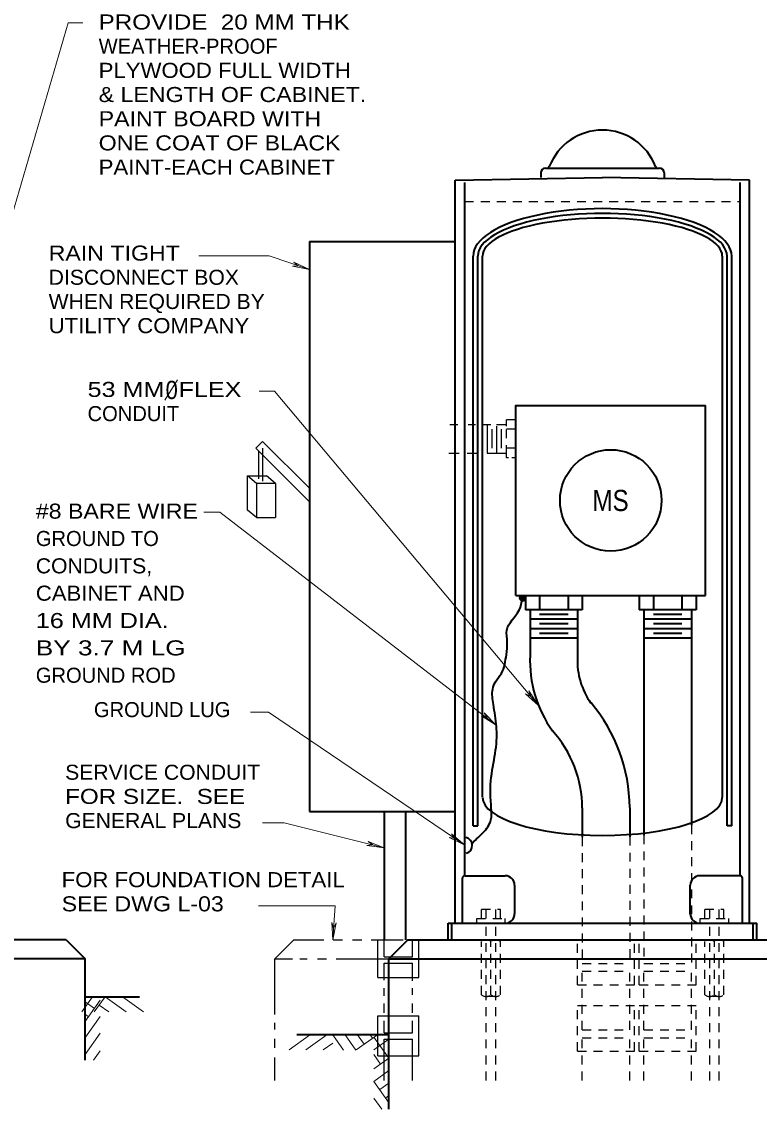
# Model space of a CAD drawing. Extents: x 312583 to 312854, y 144419 to 144597.
# Drawn here: x 312731.2 to 312768.4, y 144512.3 to 144567.2 of the extents above; entities that cross this region are included whole.
import ezdxf
from ezdxf.enums import TextEntityAlignment as Align

# ---------------------------------------------------------------- set-up
doc = ezdxf.new("R2010")
doc.units = 0
doc.header["$LTSCALE"] = 0.3
doc.linetypes.add('SHORT_DASHED', pattern=[2.7, 1.5, -1.2])
doc.layers.add('1', color=7, linetype='Continuous', lineweight=25)
doc.layers.add('2', color=7, linetype='Continuous', lineweight=13)

msp = doc.modelspace()

# ---------------------------------------------------------------- linework, layer by layer
at = {"layer": '1', "lineweight": 40}
for p, q in [((312757.3543, 144559.527), (312757.3543, 144559.2893)), ((312757.5997, 144559.7646), (312763.3497, 144559.7646)), ((312763.5873, 144559.527), (312763.5873, 144559.2893)), ((312753.0457, 144559.159), (312760.4747, 144559.2893)), ((312753.0457, 144521.6613), (312753.0457, 144559.159)), ((312753.521, 144524.061), (312753.521, 144559.044)), ((312767.896, 144559.159), (312760.4747, 144559.2893)), ((312767.4207, 144524.061), (312767.4207, 144559.044)), ((312767.896, 144521.6613), (312767.896, 144559.159)), ((312745.678, 144556.0616), (312745.678, 144527.2963)), ((312745.678, 144556.0616), (312753.0457, 144556.0616)), ((312749.2123, 144556.0616), (312750.7687, 144556.0616)), ((312753.9427, 144526.5756), (312753.9427, 144555.3256)), ((312754.1803, 144526.5756), (312754.1803, 144555.3256)), ((312754.4257, 144528.017), (312754.4257, 144555.3256)), ((312766.5237, 144528.017), (312766.5237, 144555.3256)), ((312766.7613, 144526.5756), (312766.7613, 144555.3256)), ((312766.999, 144526.5756), (312766.999, 144555.3256)), ((312765.6803, 144538.206), (312765.6803, 144547.7893)), ((312756.097, 144538.206), (312765.6803, 144538.206)), ((312756.58, 144538.206), (312756.58, 144537.4853)), ((312757.3007, 144538.206), (312757.3007, 144537.4853)), ((312758.7343, 144538.206), (312758.7343, 144537.4853)), ((312759.455, 144538.206), (312759.455, 144537.4853)), ((312762.33, 144538.206), (312762.33, 144537.4853)), ((312763.0507, 144538.206), (312763.0507, 144537.4853)), ((312764.4843, 144538.206), (312764.4843, 144537.4853)), ((312765.205, 144538.206), (312765.205, 144537.4853)), ((312759.455, 144537.4853), (312756.58, 144537.4853)), ((312756.8177, 144537.4853), (312756.8177, 144535.1776)), ((312759.2173, 144537.4853), (312759.2173, 144535.0703)), ((312765.205, 144537.4853), (312762.33, 144537.4853)), ((312762.5677, 144537.4853), (312762.5677, 144526.1003)), ((312764.9673, 144537.4853), (312764.9673, 144526.614)), ((312759.2173, 144537.01), (312756.8177, 144537.01)), ((312758.7343, 144537.2476), (312757.3007, 144537.2476)), ((312764.9673, 144537.01), (312762.5677, 144537.01)), ((312764.4843, 144537.2476), (312763.0507, 144537.2476)), ((312759.2173, 144536.527), (312756.8177, 144536.527)), ((312758.7343, 144536.7646), (312757.3007, 144536.7646)), ((312764.9673, 144536.527), (312762.5677, 144536.527)), ((312764.4843, 144536.7646), (312763.0507, 144536.7646)), ((312759.2173, 144536.0516), (312756.8177, 144536.0516)), ((312758.7343, 144536.2893), (312757.3007, 144536.2893)), ((312764.9673, 144536.0516), (312762.5677, 144536.0516)), ((312764.4843, 144536.2893), (312763.0507, 144536.2893)), ((312745.678, 144527.2963), (312753.0457, 144527.2963)), ((312749.45, 144527.2963), (312749.45, 144520.8256)), ((312750.531, 144527.2963), (312750.531, 144520.8256)), ((312759.455, 144527.4803), (312759.455, 144526.0083)), ((312761.847, 144527.4803), (312761.847, 144526.0313)), ((312753.9427, 144526.5756), (312754.1803, 144526.5756)), ((312766.999, 144526.5756), (312766.7613, 144526.5756)), ((312753.406, 144521.6613), (312753.406, 144523.9383)), ((312753.521, 144524.061), (312755.5603, 144524.061)), ((312767.4207, 144524.061), (312765.3813, 144524.061)), ((312767.5433, 144521.6613), (312767.5433, 144523.9383)), ((312756.0433, 144522.1443), (312756.0433, 144523.578)), ((312764.906, 144522.1443), (312764.906, 144523.578)), ((312752.6853, 144521.6613), (312768.2563, 144521.6613)), ((312752.6853, 144520.8256), (312752.6853, 144521.6613)), ((312752.8693, 144520.8256), (312752.8693, 144521.6613)), ((312768.08, 144520.8256), (312768.08, 144521.6613)), ((312768.2563, 144520.8256), (312768.2563, 144521.6613)), ((312733.4019, 144520.8256), (312712.3185, 144520.8256)), ((312733.4019, 144520.8256), (312734.3602, 144519.8673)), ((312750.646, 144520.8256), (312749.6877, 144519.8673)), ((312734.3602, 144519.8673), (312711.3602, 144519.8673)), ((312734.3602, 144514.746), (312734.3602, 144519.8673)), ((312749.6877, 144512.2775), (312749.6877, 144519.8673)), ((312734.3602, 144517.9506), (312737.1049, 144517.9506)), ((312749.6953, 144516.034), (312745.0417, 144516.034))]:
    msp.add_line(p, q, dxfattribs=at)
at = {"layer": '1', "linetype": 'SHORT_DASHED'}
for p, q in [((312753.521, 144558.078), (312767.4207, 144558.078)), ((312764.9673, 144526.614), (312764.9673, 144519.6373)), ((312759.455, 144526.0083), (312759.455, 144519.6373)), ((312761.847, 144526.0313), (312761.847, 144519.6373)), ((312762.5677, 144526.1003), (312762.5677, 144519.6373)), ((312754.602, 144521.9066), (312754.602, 144522.382)), ((312755.085, 144521.9066), (312755.085, 144522.382)), ((312755.3227, 144521.9066), (312755.3227, 144522.382)), ((312765.8873, 144521.9066), (312765.8873, 144522.382)), ((312766.3627, 144521.9066), (312766.3627, 144522.382)), ((312766.6003, 144521.9066), (312766.6003, 144522.382)), ((312754.1267, 144521.9066), (312755.5603, 144521.9066)), ((312754.1267, 144521.6613), (312754.1267, 144521.9066)), ((312754.602, 144513.734), (312754.602, 144521.6613)), ((312755.085, 144513.734), (312755.085, 144521.6613)), ((312755.5603, 144521.6613), (312755.5603, 144521.9066)), ((312765.4043, 144521.9066), (312766.8457, 144521.9066)), ((312765.4043, 144521.6613), (312765.4043, 144521.9066)), ((312765.8873, 144513.734), (312765.8873, 144521.6613)), ((312766.3627, 144513.734), (312766.3627, 144521.6613)), ((312766.8457, 144521.6613), (312766.8457, 144521.9066)), ((312754.3643, 144518.0503), (312754.3643, 144520.7413)), ((312754.8397, 144518.0503), (312754.8397, 144520.8256)), ((312755.3227, 144518.0503), (312755.3227, 144520.7413)), ((312759.2173, 144518.5563), (312759.2173, 144520.8256)), ((312762.0923, 144518.5563), (312762.0923, 144520.8256)), ((312762.33, 144518.5563), (312762.33, 144520.8256)), ((312765.205, 144518.5563), (312765.205, 144520.8256)), ((312765.642, 144518.0503), (312765.642, 144520.7413)), ((312766.125, 144518.0503), (312766.125, 144520.8256)), ((312766.6003, 144518.0503), (312766.6003, 144520.7413)), ((312759.455, 144519.6373), (312761.847, 144519.6373)), ((312762.5677, 144519.6373), (312764.9673, 144519.6373)), ((312759.455, 144519.2386), (312761.847, 144519.2386)), ((312759.455, 144516.287), (312759.455, 144519.2386)), ((312761.847, 144516.287), (312761.847, 144519.2386)), ((312762.5677, 144519.2386), (312764.9673, 144519.2386)), ((312762.5677, 144516.287), (312762.5677, 144519.2386)), ((312764.9673, 144516.287), (312764.9673, 144519.2386)), ((312759.2173, 144518.5563), (312762.0923, 144518.5563)), ((312762.33, 144518.5563), (312765.205, 144518.5563)), ((312755.085, 144517.9736), (312754.602, 144517.9736)), ((312766.3627, 144517.9736), (312765.8873, 144517.9736)), ((312759.2173, 144517.506), (312762.0923, 144517.506)), ((312759.2173, 144515.206), (312759.2173, 144517.506)), ((312762.0923, 144515.206), (312762.0923, 144517.506)), ((312762.33, 144517.506), (312765.205, 144517.506)), ((312762.33, 144515.206), (312762.33, 144517.506)), ((312765.205, 144515.206), (312765.205, 144517.506)), ((312759.455, 144516.287), (312761.847, 144516.287)), ((312762.5677, 144516.287), (312764.9673, 144516.287)), ((312759.455, 144515.8883), (312761.847, 144515.8883)), ((312759.455, 144513.734), (312759.455, 144515.8883)), ((312761.847, 144513.734), (312761.847, 144515.8883)), ((312762.5677, 144515.8883), (312764.9673, 144515.8883)), ((312762.5677, 144513.734), (312762.5677, 144515.8883)), ((312764.9673, 144513.734), (312764.9673, 144515.8883)), ((312759.2173, 144515.206), (312762.0923, 144515.206)), ((312762.33, 144515.206), (312765.205, 144515.206))]:
    msp.add_line(p, q, dxfattribs=at)
at = {"layer": '1'}
for p, q in [((312752.7697, 144546.831), (312753.1683, 144546.831)), ((312753.6897, 144546.831), (312754.0577, 144546.831)), ((312754.418, 144546.831), (312754.8397, 144546.831)), ((312754.6633, 144545.3896), (312754.6633, 144546.831)), ((312755.131, 144546.831), (312755.6217, 144546.831)), ((312755.1387, 144545.3896), (312755.1387, 144546.7543)), ((312756.097, 144547.0686), (312755.6217, 144547.0686)), ((312755.6217, 144546.7543), (312755.6217, 144547.0686)), ((312754.4257, 144545.635), (312754.4257, 144546.5933)), ((312754.901, 144545.635), (312754.901, 144546.5933)), ((312755.384, 144545.635), (312755.384, 144546.5933)), ((312756.097, 144546.5933), (312755.6217, 144546.5933)), ((312755.6217, 144546.1486), (312755.6217, 144546.5703)), ((312745.678, 144542.9363), (312742.9717, 144545.6426)), ((312743.3167, 144545.6426), (312743.3167, 144543.9636)), ((312755.6217, 144545.152), (312755.6217, 144545.7883)), ((312756.097, 144545.635), (312755.6217, 144545.635)), ((312743.125, 144544.094), (312743.125, 144545.5046)), ((312752.716, 144545.3896), (312753.245, 144545.3896)), ((312753.636, 144545.3896), (312754.1573, 144545.3896)), ((312754.6557, 144545.3896), (312755.6217, 144545.3896)), ((312755.729, 144545.152), (312755.6217, 144545.152)), ((312756.097, 144545.152), (312755.89, 144545.152)), ((312743.01, 144543.8563), (312742.5577, 144544.232)), ((312743.9683, 144543.8563), (312743.516, 144544.232)), ((312743.9683, 144543.8563), (312743.01, 144543.8563)), ((312743.9683, 144543.8563), (312743.9683, 144542.1313)), ((312743.01, 144542.1313), (312742.5577, 144542.507)), ((312744.896, 144520.8256), (312743.9377, 144519.8673)), ((312744.896, 144520.8256), (312746.4063, 144520.8256)), ((312746.8817, 144520.8256), (312747.3493, 144520.8256)), ((312747.8477, 144520.8256), (312748.323, 144520.8256)), ((312748.7907, 144520.8256), (312750.4083, 144520.8256)), ((312749.1357, 144518.932), (312749.1357, 144520.8256)), ((312749.45, 144519.9746), (312749.45, 144520.8256)), ((312750.8913, 144519.9746), (312750.8913, 144520.8256)), ((312751.2057, 144518.932), (312751.2057, 144520.8256)), ((312745.2027, 144519.8673), (312745.5707, 144519.8673)), ((312746.092, 144519.8673), (312746.5367, 144519.8673)), ((312747.035, 144519.8673), (312749.6877, 144519.8673)), ((312749.45, 144519.9746), (312750.8913, 144519.9746)), ((312749.45, 144519.6526), (312750.8913, 144519.6526)), ((312749.45, 144518.7863), (312749.45, 144519.6526)), ((312750.8913, 144518.7633), (312750.8913, 144519.6526)), ((312749.1357, 144518.932), (312751.2057, 144518.932)), ((312749.45, 144518.0043), (312749.45, 144518.3953)), ((312750.8913, 144518.058), (312750.8913, 144518.3953)), ((312749.45, 144517.138), (312749.45, 144517.6133)), ((312750.8913, 144517.138), (312750.8913, 144517.6133)), ((312743.9377, 144516.3023), (312743.9377, 144516.6396)), ((312749.1357, 144514.976), (312749.1357, 144516.9846)), ((312749.1357, 144516.9846), (312751.2057, 144516.9846)), ((312749.45, 144516.1336), (312749.45, 144516.747)), ((312750.8913, 144516.1336), (312750.8913, 144516.747)), ((312751.2057, 144514.976), (312751.2057, 144516.9846)), ((312749.45, 144516.1336), (312750.8913, 144516.1336)), ((312743.9377, 144515.3823), (312743.9377, 144515.827)), ((312749.45, 144515.8116), (312750.8913, 144515.8116)), ((312749.45, 144513.734), (312749.45, 144515.8116)), ((312750.8913, 144513.734), (312750.8913, 144515.8116)), ((312749.1357, 144514.976), (312751.2057, 144514.976)), ((312743.9377, 144513.734), (312743.9377, 144514.884))]:
    msp.add_line(p, q, dxfattribs=at)
at = {"layer": '1', "lineweight": 40}
for points in [[(312756.097, 144538.206), (312756.097, 144547.7893), (312765.6803, 144547.7893)], [(312750.646, 144520.8256), (312769.3932, 144520.8256), (312838.4507, 144520.8256)], [(312749.6877, 144519.8673), (312769.3932, 144519.8673), (312839.409, 144519.8673)]]:
    msp.add_lwpolyline(points, dxfattribs=at)
at = {"layer": '1'}
for points in [[(312745.678, 144543.611), (312743.3167, 144545.98), (312742.9717, 144545.6426)], [(312742.5577, 144542.507), (312742.5577, 144544.232), (312743.516, 144544.232)], [(312743.01, 144543.8563), (312743.01, 144542.1313), (312743.9683, 144542.1313)], [(312743.9377, 144517.0613), (312743.9377, 144519.8673), (312744.8347, 144519.8673)]]:
    msp.add_lwpolyline(points, dxfattribs=at)
at = {"layer": '1', "linetype": 'SHORT_DASHED'}
for points in [[(312754.3643, 144521.9066), (312754.3643, 144522.382), (312755.3227, 144522.382)], [(312765.642, 144521.9066), (312765.642, 144522.382), (312766.6003, 144522.382)]]:
    msp.add_lwpolyline(points, dxfattribs=at)
at = {"layer": '1', "lineweight": 40}
for centre, radius in [((312760.8915, 144542.9967), 2.5622), ((312756.443, 144538.0651), 0.1358), ((312756.443, 144538.0651), 0.1174), ((312756.443, 144538.0651), 0.1057), ((312756.443, 144538.0651), 0.0822), ((312756.443, 144538.0651), 0.0575), ((312756.443, 144538.0651), 0.0403), ((312756.443, 144538.0651), 0.0282), ((312756.443, 144538.0651), 0.0197), ((312756.443, 144538.0651), 0.0138)]:
    msp.add_circle(centre, radius, dxfattribs=at)
for centre, radius, start, end in [((312760.4718, 144558.8092), 2.875, 21.1002, 158.90079), ((312757.5968, 144559.5279), 0.2396, 90, 180), ((312757.6778, 144559.8873), 0.1198, 270, 338.8998), ((312763.2658, 144559.8873), 0.1198, 201.1002, 270), ((312763.3468, 144559.5279), 0.2396, 0, 90), ((312762.864, 144534.9026), 6.0515, 177.41325, 215.63484), ((312762.864, 144534.9026), 3.6557, 177.41325, 215.63484), ((312753.5213, 144527.4239), 8.3288, 0.55271, 40.01494), ((312753.5213, 144527.4239), 5.933, 0.55379, 41.7798), ((312753.494, 144525.5862), 0.4076, 285.15764, 77.61644), ((312753.5239, 144523.9402), 0.1198, 90, 180), ((312755.5603, 144523.5808), 0.4792, 0, 90), ((312765.3833, 144523.5808), 0.4792, 90, 180), ((312767.4197, 144523.9402), 0.1198, 0, 90), ((312755.5603, 144522.1433), 0.4792, 270, 0), ((312765.3833, 144522.1433), 0.4792, 180, 270)]:
    msp.add_arc(centre, radius, start, end, dxfattribs=at)
at = {"layer": '1', "linetype": 'SHORT_DASHED'}
for centre, radius, start, end in [((312754.602, 144520.4379), 0.3858, 51.61151, 128.38849), ((312755.0812, 144520.4045), 0.4125, 54.49327, 125.50673), ((312765.8835, 144520.4379), 0.3858, 51.61151, 128.38849), ((312766.3627, 144520.4045), 0.4125, 54.49327, 125.50673), ((312754.602, 144518.3823), 0.4125, 234.49327, 305.50673), ((312755.0812, 144518.3823), 0.4125, 234.49327, 305.50673), ((312765.8835, 144518.3823), 0.4125, 234.49327, 305.50673), ((312766.3627, 144518.3823), 0.4125, 234.49327, 305.50673)]:
    msp.add_arc(centre, radius, start, end, dxfattribs=at)
at = {"layer": '1', "lineweight": 40}
for centre, major_axis, ratio, start_param, end_param in [((312760.4723, 144555.3256), (6.5286, 0), 0.366972, 6.2831853, 9.424778), ((312760.4723, 144555.3256), (6.2891, 0), 0.342857, 6.2831853, 9.424778), ((312760.4723, 144555.3256), (6.0495, 0), 0.316832, 6.2831853, 9.424778), ((312760.4723, 144528.0131), (6.0495, 0), 0.316832, 3.1415927, 6.2831853)]:
    msp.add_ellipse(centre, major_axis=major_axis, ratio=ratio, start_param=start_param, end_param=end_param, dxfattribs=at)
msp.add_spline([(312753.889, 144525.694), (312754.119, 144525.9163), (312754.4563, 144526.2383), (312754.8397, 144526.8746), (312754.8627, 144527.488), (312754.8167, 144528.3006), (312754.97, 144529.742), (312755.1387, 144531.0376), (312755.0543, 144532.1416), (312754.97, 144532.7013), (312754.9317, 144533.4833), (312755.0697, 144533.8436), (312755.3687, 144534.273), (312755.6217, 144535.2083), (312755.6677, 144535.8446), (312755.6447, 144536.458), (312756.2657, 144537.4623), (312756.442, 144538.068)], degree=3, dxfattribs=at)
at = {"layer": '2'}
for p, q in [((312733.5012, 144567.0972), (312728.8555, 144551.1933)), ((312734.2372, 144567.0972), (312733.5012, 144567.0972)), ((312743.6463, 144555.3333), (312740.1043, 144555.3333)), ((312745.678, 144554.6433), (312743.6463, 144555.3333)), ((312744.896, 144555.0266), (312745.1183, 144554.835)), ((312745.678, 144554.6433), (312744.896, 144555.0266)), ((312744.8193, 144554.8196), (312745.1183, 144554.835)), ((312745.678, 144554.6433), (312744.8193, 144554.8196)), ((312738.3844, 144548.0607), (312739.0207, 144549.0804)), ((312741.1523, 144542.4038), (312740.3596, 144542.4038)), ((312741.1523, 144542.4038), (312755.108, 144531.6663)), ((312756.5953, 144533.2456), (312756.8637, 144533.1076)), ((312757.247, 144532.6553), (312756.5953, 144533.2456)), ((312756.764, 144533.3913), (312756.8637, 144533.1076)), ((312757.247, 144532.6553), (312756.764, 144533.3913)), ((312742.7124, 144532.3103), (312743.6233, 144532.3103)), ((312743.6233, 144532.3103), (312753.521, 144525.6096)), ((312754.3643, 144532.1263), (312754.6557, 144532.0343)), ((312755.108, 144531.6663), (312754.3643, 144532.1263)), ((312754.5023, 144532.2873), (312754.6557, 144532.0343)), ((312755.108, 144531.6663), (312754.5023, 144532.2873)), ((312743.3167, 144526.7366), (312744.4053, 144526.7366)), ((312744.4053, 144526.7366), (312749.45, 144525.464)), ((312752.739, 144525.9853), (312753.0303, 144525.9316)), ((312753.521, 144525.6096), (312752.739, 144525.9853)), ((312752.854, 144526.1693), (312753.0303, 144525.9316)), ((312753.521, 144525.6096), (312752.854, 144526.1693)), ((312748.5837, 144525.5866), (312748.8827, 144525.6173)), ((312749.45, 144525.464), (312748.5837, 144525.5866)), ((312748.645, 144525.7936), (312748.8827, 144525.6173)), ((312749.45, 144525.464), (312748.645, 144525.7936)), ((312743.1135, 144522.543), (312746.989, 144522.543)), ((312746.989, 144522.543), (312746.8663, 144520.8563)), ((312746.8203, 144521.6996), (312746.9047, 144521.416)), ((312746.8663, 144520.8256), (312746.8203, 144521.6996)), ((312746.8663, 144520.8256), (312747.035, 144521.6843)), ((312747.035, 144521.6843), (312746.9047, 144521.416)), ((312734.7359, 144517.9506), (312734.1915, 144517.1916)), ((312735.1269, 144517.782), (312734.3525, 144516.6933)), ((312734.3602, 144517.6976), (312734.8279, 144517.368)), ((312735.3645, 144517.9506), (312734.8202, 144517.1916)), ((312736.4302, 144517.1916), (312735.3645, 144517.9506)), ((312737.3119, 144517.1916), (312736.2462, 144517.9506)), ((312735.5562, 144517.1916), (312735.0655, 144517.5366)), ((312734.3602, 144517.069), (312734.5289, 144516.9463)), ((312735.1269, 144516.954), (312734.3832, 144515.9113)), ((312735.1269, 144516.1106), (312734.3602, 144515.0373)), ((312744.6507, 144515.275), (312745.6933, 144516.011)), ((312745.494, 144515.275), (312746.5673, 144516.034)), ((312746.8587, 144516.0263), (312747.403, 144515.2596)), ((312747.4873, 144516.0263), (312748.0317, 144515.2596)), ((312748.047, 144515.275), (312749.1127, 144516.034)), ((312748.116, 144516.0263), (312748.4457, 144515.5586)), ((312748.7447, 144516.0263), (312748.8597, 144515.8576)), ((312749.358, 144516.034), (312749.358, 144516.0416)), ((312746.3757, 144515.275), (312746.8587, 144515.62)), ((312748.9287, 144515.919), (312749.6953, 144514.8533)), ((312748.9287, 144515.275), (312749.6953, 144515.8193)), ((312735.1269, 144515.229), (312734.7819, 144514.746)), ((312748.9287, 144515.0373), (312749.2737, 144514.5543)), ((312749.6953, 144514.8533), (312748.9287, 144514.309)), ((312749.6953, 144514.2246), (312748.9287, 144513.6803)), ((312748.9287, 144513.6803), (312749.703, 144512.5916)), ((312749.6953, 144513.596), (312749.2277, 144513.2663)), ((312748.9287, 144512.8446), (312749.3361, 144512.2775)), ((312749.6953, 144512.9673), (312749.519, 144512.8446))]:
    msp.add_line(p, q, dxfattribs=at)
msp.add_lwpolyline([(312743.148, 144548.5176), (312743.9223, 144548.5176), (312757.247, 144532.6553)], dxfattribs=at)

# ---------------------------------------------------------------- texts
at = {"layer": '1'}
for s, p in [('GROUND TO', (312731.8702, 144540.6983)), ('GROUND ROD', (312731.8702, 144533.7983))]:
    msp.add_text(s, height=0.76, dxfattribs=at).set_placement(p)
for s, width, p in [('CONDUITS,', 1.05, (312731.8702, 144539.3183)), ('CABINET AND', 1.1, (312731.8702, 144537.9383)), ('16 MM DIA.', 1.25, (312731.8702, 144536.5583)), ('BY 3.7 M LG', 1.3, (312731.8702, 144535.1783))]:
    msp.add_text(s, height=0.76, dxfattribs=dict(at, width=width)).set_placement(p)
at = {"layer": '2'}
for s, width, p in [('PROVIDE  20 MM THK', 1.2, (312735.0431, 144566.7604)), ('PLYWOOD FULL WIDTH', 1.1, (312735.0431, 144564.3204)), ('& LENGTH OF CABINET.', 1.15, (312735.0431, 144563.1004)), ('PAINT BOARD WITH', 1.15, (312735.0431, 144561.8804)), ('ONE COAT OF BLACK', 1.15, (312735.0431, 144560.6604)), ('PAINT-EACH CABINET', 1.1, (312735.0431, 144559.4404)), ('RAIN TIGHT', 1.15, (312732.5186, 144555.0989)), ('DISCONNECT BOX', 1.05, (312732.5186, 144553.8789)), ('WHEN REQUIRED BY', 1.05, (312732.5186, 144552.6589)), ('UTILITY COMPANY', 1.1, (312732.5186, 144551.4389)), ('53 MM  FLEX', 1.25, (312734.4834, 144548.2208)), ('#8 BARE WIRE', 1.15, (312731.8702, 144542.0783)), ('SERVICE CONDUIT', 1.05, (312733.3523, 144528.9027)), ('FOR SIZE.  SEE', 1.2, (312733.3523, 144527.6827)), ('GENERAL PLANS', 1.05, (312733.3523, 144526.4627)), ('FOR FOUNDATION DETAIL', 1.1, (312733.1754, 144523.4832)), ('SEE DWG L-03', 1.15, (312733.1754, 144522.2632))]:
    msp.add_text(s, height=0.76, dxfattribs=dict(at, width=width)).set_placement(p)
for s, p in [('WEATHER-PROOF', (312735.0431, 144565.5404)), ('CONDUIT', (312734.4834, 144547.0008)), ('GROUND LUG', (312734.8037, 144532.064))]:
    msp.add_text(s, height=0.76, dxfattribs=at).set_placement(p)
for s, height, width, p in [('0', 0.92, 0.9, (312738.7294, 144548.1144)), ('MS', 1.072, 0.85, (312760.881, 144542.461))]:
    msp.add_text(s, height=height, dxfattribs=dict(at, width=width)).set_placement(p, align=Align.CENTER)

doc.saveas('drawing.dxf')
